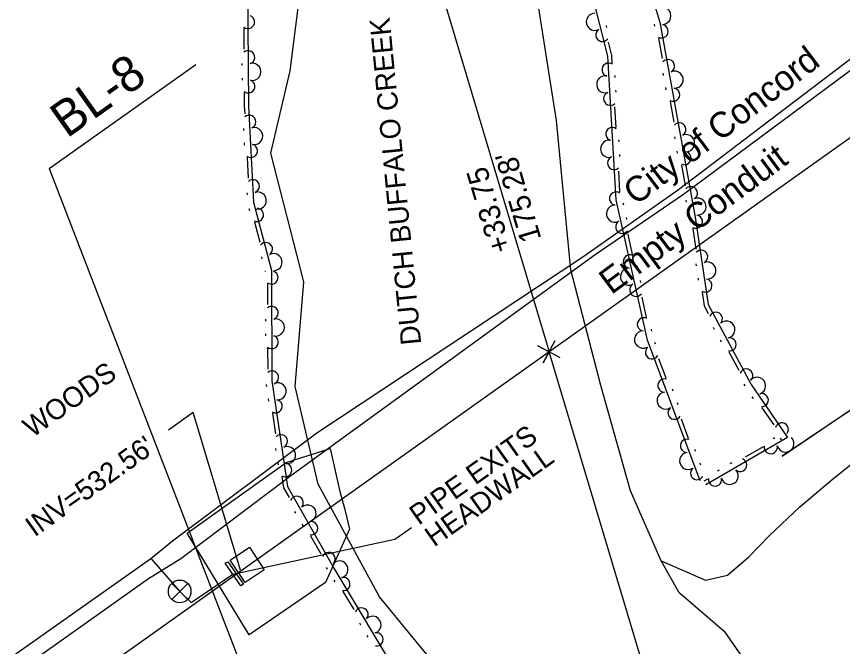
# Model space of a CAD drawing. Extents: x 1577032 to 1581865, y 611492 to 615011.
# Drawn here: x 1579630.9 to 1579793.8, y 613356.4 to 613480.5 of the extents above; entities that cross this region are included whole.
import ezdxf

# ---------------------------------------------------------------- set-up
doc = ezdxf.new("R2010")
doc.units = 0
for name, color, linetype in [('Exist Horizontal Baseline Alignment Station Label', 7, 'Continuous'), ('Exist Hydro Jurisdictional Stream or Body of Water', 7, 'Continuous'), ('Exist Hydro Jurisdictional Stream or Body of Water Text', 7, 'Continuous'), ('Exist Other Culture Area Outline', 7, 'Continuous'), ('Exist Other Culture Fence Line', 7, 'Continuous'), ('Exist Property Corner CELL', 7, 'Continuous'), ('Exist Property Line', 7, 'Continuous'), ('Exist Property Tie Line', 7, 'Continuous'), ('Exist Property Tie Line Text', 7, 'Continuous'), ('Exist Right of Way Line', 7, 'Continuous'), ('Exist Roads EOP Other', 7, 'Continuous'), ('Exist Structure Minor Head and End Wall', 7, 'Continuous'), ('Exist Structure Minor Pipes CMP 12 Inch Invert', 7, 'Continuous'), ('Exist Structure Minor Pipes CMP 18 Inch Leader', 7, 'Continuous'), ('Exist Utilities Telephone UG FO SUE LOS B', 7, 'Continuous'), ('Exist Utilities Telephone UG FO SUE LOS B Text', 7, 'Continuous'), ('Exist Utilities Water UG Line SUE LOS B', 7, 'Continuous'), ('Exist Utilities Water UG Line SUE LOS B Leader', 7, 'Continuous'), ('Exist Utilities Water UG Line SUE LOS B Text', 7, 'Continuous'), ('Exist Utilities Water Valve CELL', 7, 'Continuous'), ('Exist Vegetation Woods Line Text', 7, 'Continuous'), ('Old_Level_11', 7, 'Continuous'), ('Old_Level_8', 7, 'Continuous')]:
    doc.layers.add(name, color=color, linetype=linetype)

msp = doc.modelspace()

# ---------------------------------------------------------------- linework, layer by layer
at = {"layer": 'Exist Horizontal Baseline Alignment Station Label'}
for q in [(1579666.25, 613471.06), (1579698.95, 613291.12)]:
    msp.add_line((1579637.33, 613450.53), q, dxfattribs=at)
at = {"layer": 'Exist Hydro Jurisdictional Stream or Body of Water'}
for points in [[(1579761.5, 613367.04), (1579757.97, 613373.23), (1579751.93, 613387.05), (1579746.09, 613407.81), (1579740.21, 613430.58), (1579737.36, 613460), (1579733.31, 613485.96), (1579729.5, 613507.35), (1579726.38, 613528.01), (1579726.03, 613549.45), (1579721.99, 613586.55), (1579715.12, 613622.69)], [(1579725.68, 613337.86), (1579702.45, 613366.13), (1579690.36, 613388.32), (1579685.84, 613407.56), (1579687.53, 613428.23), (1579681.01, 613453.54), (1579684.84, 613469.8), (1579686.57, 613483.26), (1579683.27, 613517.5), (1579681.81, 613542.23), (1579681.11, 613568.29), (1579677.24, 613598.35)], [(1579757.97, 613373.23), (1579766.74, 613369.43), (1579771.07, 613370.41), (1579775.3, 613374.04), (1579779.35, 613378.24), (1579785.35, 613383.89), (1579792.13, 613389.6), (1579798.96, 613395.04)], [(1579761.5, 613367.04), (1579770.44, 613359.38), (1579780.93, 613344.22)]]:
    msp.add_lwpolyline(points, dxfattribs=at)
at = {"layer": 'Exist Other Culture Area Outline'}
msp.add_lwpolyline([(1579691.81, 613368.97), (1579676.74, 613358.68), (1579664.51, 613378.71), (1579684.01, 613392.6), (1579692.7, 613395.35), (1579694.57, 613387.18), (1579695.64, 613383.35), (1579696.55, 613379.49), (1579691.81, 613368.97)], dxfattribs=at)
at = {"layer": 'Exist Other Culture Fence Line'}
msp.add_line((1579781.84, 613393.87), (1580062.36, 613584.21), dxfattribs=at)
at = {"layer": 'Exist Property Corner CELL'}
msp.add_line((1579735.91, 613414.45), (1579735.91, 613414.45), dxfattribs=at)
msp.add_lwpolyline([(1579738.11, 613413.26), (1579733.71, 613415.63), (1579735.91, 613414.45), (1579734.72, 613412.25), (1579737.09, 613416.65)], dxfattribs=at)
at = {"layer": 'Exist Property Line'}
msp.add_line((1579616.58, 613813.08), (1579735.91, 613414.45), dxfattribs=at)
at = {"layer": 'Exist Property Tie Line'}
msp.add_line((1579786.17, 613246.53), (1579735.91, 613414.45), dxfattribs=at)
at = {"layer": 'Exist Right of Way Line'}
msp.add_line((1579178.76, 613018.8), (1580074.87, 613655.16), dxfattribs=at)
at = {"layer": 'Exist Roads EOP Other'}
msp.add_lwpolyline([(1579672.99, 613373.34), (1579676.78, 613375.94), (1579679.72, 613371.46), (1579675.93, 613368.96), (1579672.99, 613373.34)], dxfattribs=at)
at = {"layer": 'Exist Structure Minor Head and End Wall'}
msp.add_lwpolyline([(1579672.54, 613373.02), (1579675.6, 613368.61), (1579675.13, 613368.3), (1579672.02, 613372.74), (1579672.54, 613373.02)], dxfattribs=at)
at = {"layer": 'Exist Structure Minor Pipes CMP 18 Inch Leader'}
msp.add_lwpolyline([(1579675.03, 613371.38), (1579665.72, 613402.48), (1579660.83, 613399.01)], dxfattribs=at)
at = {"layer": 'Exist Utilities Telephone UG FO SUE LOS B'}
msp.add_lwpolyline([(1579251.42, 613079.81), (1579314.27, 613123.97), (1579356.61, 613152.5), (1579497.4, 613253.81), (1579521.61, 613271), (1579539.5, 613284.38), (1579578.9, 613312.67), (1579610.42, 613336.81), (1579656.92, 613369.78), (1579663.28, 613373.7), (1579685.42, 613390.38), (1579744.99, 613433.57), (1579762.43, 613445.5), (1579805.52, 613477.49)], dxfattribs=at)
at = {"layer": 'Exist Utilities Water UG Line SUE LOS B'}
for p, q in [((1579761.45, 613446.42), (1579804.35, 613479.02)), ((1579742.52, 613433.11), (1579761.45, 613446.42)), ((1579690.1, 613398.48), (1579742.52, 613433.11)), ((1579661.62, 613377.18), (1579690.1, 613398.48)), ((1579657.38, 613373.69), (1579661.62, 613377.18)), ((1579608.93, 613339.63), (1579657.38, 613373.69)), ((1579657.38, 613373.69), (1579663.06, 613367.21)), ((1579665.28, 613365.03), (1579673.54, 613370.61)), ((1579663.06, 613367.21), (1579665.28, 613365.03))]:
    msp.add_line(p, q, dxfattribs=at)
at = {"layer": 'Exist Utilities Water UG Line SUE LOS B Leader'}
msp.add_lwpolyline([(1579673.54, 613370.61), (1579705.45, 613377.47), (1579708.76, 613379.82)], dxfattribs=at)
at = {"layer": 'Exist Utilities Water Valve CELL'}
msp.add_lwpolyline([(1579664.62, 613368.78), (1579661.47, 613365.63), (1579663.04, 613367.21), (1579664.62, 613365.63), (1579661.47, 613368.78)], dxfattribs=at)
msp.add_circle((1579663.04, 613367.21), 2.23, dxfattribs=at)
at = {"layer": 'Old_Level_11'}
for points in [[(1579668.31, 613574.9), (1579674.96, 613547.45), (1579676.53, 613532.3), (1579675.8, 613513.47), (1579676.54, 613496.46), (1579676.51, 613478.85), (1579676.6, 613462.83), (1579677.63, 613443.92), (1579681.14, 613430.42), (1579681.23, 613408.68), (1579684.32, 613387.86), (1579693.46, 613371.76), (1579706.72, 613349.62), (1579642.32, 613306.79), (1579612.01, 613348.24), (1579582.34, 613397.36), (1579537.68, 613478.58)], [(1579765.67, 613388.97), (1579755.29, 613416.71), (1579749.14, 613444.35), (1579747.47, 613472.67), (1579741.11, 613498), (1579738.42, 613517.79), (1579737, 613533.96), (1579742.59, 613531.44), (1579748.06, 613511.06), (1579757.77, 613479.36), (1579764.72, 613440.99), (1579767.29, 613423.73), (1579775.74, 613407.98), (1579782.89, 613397.51), (1579766.82, 613388.19)], [(1579675.69, 613478.2), (1579675.71, 613474.1)], [(1579747.31, 613478.36), (1579747.21, 613478.76)], [(1579756.59, 613479), (1579756.66, 613478.59)], [(1579757.5, 613476.24), (1579758.23, 613472.21)], [(1579748.37, 613471.31), (1579748.28, 613472.8), (1579747.61, 613475.48)], [(1579675.32, 613471.23), (1579675.32, 613470.82)], [(1579675.34, 613468.35), (1579675.34, 613467.94)], [(1579748.95, 613468.47), (1579748.92, 613468.88)], [(1579758.34, 613469.31), (1579758.41, 613468.91)], [(1579758.85, 613466.49), (1579758.93, 613466.08)], [(1579675.76, 613465.49), (1579675.78, 613462.81), (1579675.86, 613461.35)], [(1579749.12, 613465.6), (1579749.09, 613466.01)], [(1579759.77, 613463.73), (1579760.5, 613459.7)], [(1579749.12, 613458.62), (1579748.88, 613462.71)], [(1579675.61, 613458.46), (1579675.63, 613458.05)], [(1579760.61, 613456.8), (1579760.68, 613456.4)], [(1579675.76, 613455.59), (1579675.79, 613455.18)], [(1579749.69, 613455.78), (1579749.67, 613456.19)], [(1579749.86, 613452.91), (1579749.84, 613453.32)], [(1579761.12, 613453.97), (1579761.19, 613453.57)], [(1579676.33, 613452.75), (1579676.55, 613448.65)], [(1579749.86, 613445.93), (1579749.62, 613450.02)], [(1579762.03, 613451.22), (1579762.76, 613447.19)], [(1579676.3, 613445.77), (1579676.32, 613445.36)], [(1579750.63, 613443.31), (1579750.54, 613443.71)], [(1579762.87, 613444.29), (1579762.95, 613443.89)], [(1579676.68, 613442.68), (1579676.79, 613442.29)], [(1579751.25, 613440.51), (1579751.16, 613440.91)], [(1579763.38, 613441.47), (1579763.46, 613441.06)], [(1579677.8, 613440.01), (1579678.83, 613436.04)], [(1579764.23, 613438.73), (1579764.83, 613434.67)], [(1579752.37, 613433.61), (1579751.48, 613437.62)], [(1579679.16, 613433.16), (1579679.26, 613432.76)], [(1579679.88, 613430.38), (1579679.91, 613430.26), (1579679.91, 613430.28)], [(1579753.39, 613430.9), (1579753.3, 613431.3)], [(1579764.85, 613431.77), (1579764.91, 613431.37)], [(1579765.27, 613428.93), (1579765.33, 613428.53)], [(1579680.33, 613427.82), (1579680.35, 613423.72)], [(1579754.02, 613428.1), (1579753.93, 613428.5)], [(1579766.1, 613426.15), (1579766.49, 613423.46), (1579767.28, 613421.99)], [(1579755.13, 613421.2), (1579754.24, 613425.21)], [(1579679.95, 613420.85), (1579679.95, 613420.44)], [(1579756.16, 613418.49), (1579756.07, 613418.89)], [(1579768.28, 613419.27), (1579768.47, 613418.91)], [(1579679.96, 613417.98), (1579679.96, 613417.57)], [(1579756.91, 613415.9), (1579756.76, 613416.29)], [(1579769.64, 613416.74), (1579769.83, 613416.38)], [(1579680.38, 613415.11), (1579680.4, 613411.01)], [(1579771.36, 613414.41), (1579773.3, 613410.79)], [(1579758.97, 613409.23), (1579757.53, 613413.07)], [(1579680.09, 613407.97), (1579680.15, 613407.56)], [(1579774.29, 613408.07), (1579774.49, 613407.71)], [(1579760.36, 613406.69), (1579760.21, 613407.07)], [(1579680.52, 613405.13), (1579680.58, 613404.72)], [(1579761.36, 613404), (1579761.22, 613404.38)], [(1579775.91, 613405.54), (1579776.14, 613405.21)], [(1579777.87, 613403.41), (1579780.19, 613400.02)], [(1579681.34, 613402.35), (1579681.95, 613398.29)], [(1579763.42, 613397.32), (1579761.98, 613401.17)], [(1579780.42, 613397.5), (1579780.07, 613397.3)], [(1579781.47, 613397.42), (1579781.7, 613397.08)], [(1579681.96, 613395.39), (1579682.02, 613394.99)], [(1579764.81, 613394.78), (1579764.67, 613395.17)], [(1579778.15, 613395.71), (1579774.6, 613393.65)], [(1579682.38, 613392.55), (1579682.44, 613392.15)], [(1579765.82, 613392.09), (1579765.67, 613392.47)], [(1579771.91, 613392.57), (1579771.56, 613392.36)], [(1579683.21, 613389.77), (1579683.54, 613387.59), (1579684.62, 613385.68)], [(1579769.43, 613391.13), (1579769.07, 613390.92)], [(1579767.15, 613389.33), (1579766.41, 613388.9)], [(1579685.68, 613382.98), (1579685.88, 613382.62)], [(1579687.1, 613380.48), (1579687.3, 613380.12)], [(1579688.87, 613378.19), (1579690.89, 613374.62)], [(1579691.96, 613371.92), (1579692.16, 613371.56)], [(1579693.43, 613369.42), (1579693.64, 613369.07)], [(1579695.25, 613367.17), (1579697.36, 613363.65)], [(1579698.48, 613360.98), (1579698.69, 613360.63)], [(1579699.96, 613358.52), (1579700.17, 613358.16)]]:
    msp.add_lwpolyline(points, dxfattribs=at)
for centre, radius, start, end in [((1579744.92, 613479.45), 1.69, 90.0563, 298.1288), ((1579758.24, 613480.64), 1.69, 273.0029, 121.0754), ((1579676.51, 613479.43), 1.3, 230.6671, 71.4636), ((1579746.41, 613476.87), 1.3, 122.5275, 323.3241), ((1579758.09, 613477.6), 1.3, 241.0359, 81.8325), ((1579676.54, 613472.46), 1.3, 288.7695, 129.5661), ((1579677.38, 613469.6), 1.69, 256.2983, 104.3708), ((1579747.62, 613470.03), 1.3, 54.1423, 254.9389), ((1579759.33, 613470.74), 1.3, 298.7024, 139.499), ((1579760.65, 613468.06), 1.69, 266.2312, 114.3037), ((1579676.58, 613466.72), 1.3, 231.103, 71.8996), ((1579746.97, 613467.12), 1.69, 79.3376, 287.4101), ((1579760.36, 613465.09), 1.3, 241.0359, 81.8325), ((1579747.96, 613464.3), 1.3, 111.8088, 312.6054), ((1579676.77, 613459.75), 1.3, 291.5655, 132.3621), ((1579677.74, 613456.93), 1.69, 259.0943, 107.1668), ((1579748.37, 613457.34), 1.3, 54.1423, 254.9389), ((1579761.6, 613458.23), 1.3, 298.7024, 139.499), ((1579762.92, 613455.55), 1.69, 266.2312, 114.3037), ((1579677.08, 613454.02), 1.3, 233.899, 74.6956), ((1579747.72, 613454.43), 1.69, 79.3376, 287.4101), ((1579762.62, 613452.58), 1.3, 241.0359, 81.8325), ((1579748.71, 613451.61), 1.3, 111.8088, 312.6054), ((1579677.46, 613447.06), 1.3, 291.5655, 132.3621), ((1579763.86, 613445.72), 1.3, 298.7024, 139.499), ((1579678.44, 613444.24), 1.69, 259.0943, 107.1668), ((1579749.12, 613444.65), 1.3, 54.1423, 254.9389), ((1579748.89, 613441.66), 1.69, 88.5192, 296.5917), ((1579765.18, 613443.04), 1.69, 266.2312, 114.3037), ((1579678.29, 613441.41), 1.3, 245.3375, 86.1341), ((1579750.32, 613439.04), 1.3, 120.9904, 321.787), ((1579764.86, 613440.07), 1.3, 239.2138, 80.0104), ((1579680.04, 613434.66), 1.3, 303.004, 143.8005), ((1579681.56, 613432.09), 1.69, 270.5328, 118.6052), ((1579765.88, 613433.17), 1.3, 296.8803, 137.6768), ((1579751.83, 613432.23), 1.3, 63.3239, 264.1205), ((1579767.12, 613430.45), 1.69, 264.4091, 112.4816), ((1579681.15, 613429.06), 1.3, 231.0063, 71.8028), ((1579751.66, 613429.25), 1.69, 88.5192, 296.5917), ((1579766.73, 613427.49), 1.3, 239.2138, 80.0104), ((1579753.08, 613426.63), 1.3, 120.9904, 321.787), ((1579681.18, 613422.09), 1.3, 288.6727, 129.4693), ((1579768.78, 613420.94), 1.3, 316.6627, 157.4593), ((1579682.01, 613419.22), 1.69, 256.2015, 104.274), ((1579754.6, 613419.83), 1.3, 63.3239, 264.1205), ((1579770.86, 613418.8), 1.69, 284.1915, 132.264), ((1579681.2, 613416.35), 1.3, 231.0063, 71.8028), ((1579754.42, 613416.84), 1.69, 88.5192, 296.5917), ((1579771.5, 613415.88), 1.3, 258.9962, 99.7928), ((1579756.19, 613414.32), 1.3, 128.9516, 329.7482), ((1579774.79, 613409.74), 1.3, 316.6627, 157.4593), ((1579681.23, 613409.37), 1.3, 288.6727, 129.4693), ((1579776.91, 613407.72), 1.69, 290.3274, 138.3998), ((1579682.36, 613406.65), 1.69, 264.4102, 112.4827), ((1579758.63, 613407.79), 1.3, 71.2852, 272.0817), ((1579758.87, 613404.82), 1.69, 96.4804, 304.5529), ((1579777.85, 613404.89), 1.3, 265.1321, 105.9286), ((1579681.97, 613403.69), 1.3, 239.2149, 80.0115), ((1579760.64, 613402.41), 1.3, 128.9516, 329.7482), ((1579781.79, 613399.13), 1.3, 322.7985, 163.5951), ((1579683, 613396.79), 1.3, 296.8814, 137.678), ((1579763.08, 613395.89), 1.3, 71.2852, 272.0817), ((1579782.52, 613396.35), 1.69, 196.0691, 44.1416), ((1579684.23, 613394.07), 1.69, 264.4102, 112.4827), ((1579763.32, 613392.91), 1.69, 96.4804, 304.5529), ((1579779.62, 613395.62), 1.3, 170.8738, 11.6704), ((1579773.59, 613392.12), 1.3, 228.5403, 69.3369), ((1579683.84, 613391.11), 1.3, 239.2149, 80.0115), ((1579765.1, 613390.51), 1.3, 128.9516, 329.7482), ((1579771.52, 613389.97), 1.69, 196.0691, 44.1416), ((1579768.63, 613389.24), 1.3, 170.8738, 11.6704), ((1579686.14, 613384.66), 1.3, 318.0126, 158.8092), ((1579688.27, 613382.56), 1.69, 285.5414, 133.6139), ((1579688.98, 613379.66), 1.3, 260.3461, 101.1427), ((1579692.42, 613373.6), 1.3, 318.0126, 158.8092), ((1579694.55, 613371.53), 1.69, 286.8791, 134.9516), ((1579695.33, 613368.65), 1.3, 261.6838, 102.4804), ((1579698.91, 613362.67), 1.3, 319.3503, 160.1469), ((1579701.09, 613360.63), 1.69, 286.8791, 134.9516), ((1579701.86, 613357.74), 1.3, 261.6838, 102.4804)]:
    msp.add_arc(centre, radius, start, end, dxfattribs=at)
at = {"layer": 'Old_Level_8'}
msp.add_lwpolyline([(1580005.94, 613678.54), (1580001.69, 613675.94), (1580063.69, 613587.13), (1579885.94, 613463.7), (1579781.84, 613393.87)], dxfattribs=at)

# ---------------------------------------------------------------- texts
at = {"layer": 'Exist Horizontal Baseline Alignment Station Label'}
msp.add_text('BL-8', height=7, rotation=35.38, dxfattribs=at).set_placement((1579640.81, 613456.4))
at = {"layer": 'Exist Hydro Jurisdictional Stream or Body of Water Text'}
msp.add_text('DUTCH BUFFALO CREEK', height=4, rotation=95.5451, dxfattribs=at).set_placement((1579710.69, 613415.96))
at = {"layer": 'Exist Property Tie Line Text'}
for s, p in [("175.28'", (1579734.41, 613436.73)), ('+33.75', (1579728.47, 613434.61))]:
    msp.add_text(s, height=4.2, rotation=106.6644, dxfattribs=at).set_placement(p)
at = {"layer": 'Exist Structure Minor Pipes CMP 12 Inch Invert'}
msp.add_text("INV=532.56'", height=4, rotation=35.38, dxfattribs=at).set_placement((1579634.44, 613377.82))
at = {"layer": 'Exist Utilities Telephone UG FO SUE LOS B Text'}
msp.add_text('Empty Conduit', height=5, rotation=36.5911, dxfattribs=at).set_placement((1579748.17, 613425.57))
at = {"layer": 'Exist Utilities Water UG Line SUE LOS B Text'}
for s, height, rotation, p in [('City of Concord', 5, 37.2324, (1579753, 613443.14)), ('PIPE EXITS', 4, 35.38, (1579710.19, 613380.13)), ('HEADWALL', 4, 35.38, (1579713.23, 613375.85))]:
    msp.add_text(s, height=height, rotation=rotation, dxfattribs=at).set_placement(p)
at = {"layer": 'Exist Vegetation Woods Line Text'}
msp.add_text('WOODS', height=4, rotation=35.38, dxfattribs=at).set_placement((1579633.98, 613397.39))

doc.saveas('drawing.dxf')
